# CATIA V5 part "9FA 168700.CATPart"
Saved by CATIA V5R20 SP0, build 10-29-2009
Part number: 9FA 168700
Revision: ANY
Definition: UNKNOWN
Nomenclature: 9FA 168700
Source: Unknown
Bounding box of the stored display mesh (mm): x -8 to 8, y 0.13 to 20.13, z -8 to 8
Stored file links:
  C:\Users\Utente\Desktop\IO LAVORO\3D X SITO CF\CUMSA\3D files FA\FA 168700\9FA 168700.CATPart
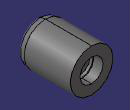
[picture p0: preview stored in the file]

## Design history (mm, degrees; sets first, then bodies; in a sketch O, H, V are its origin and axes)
Body1 "Redondeo1" (main body)
  Solid1: solid without history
